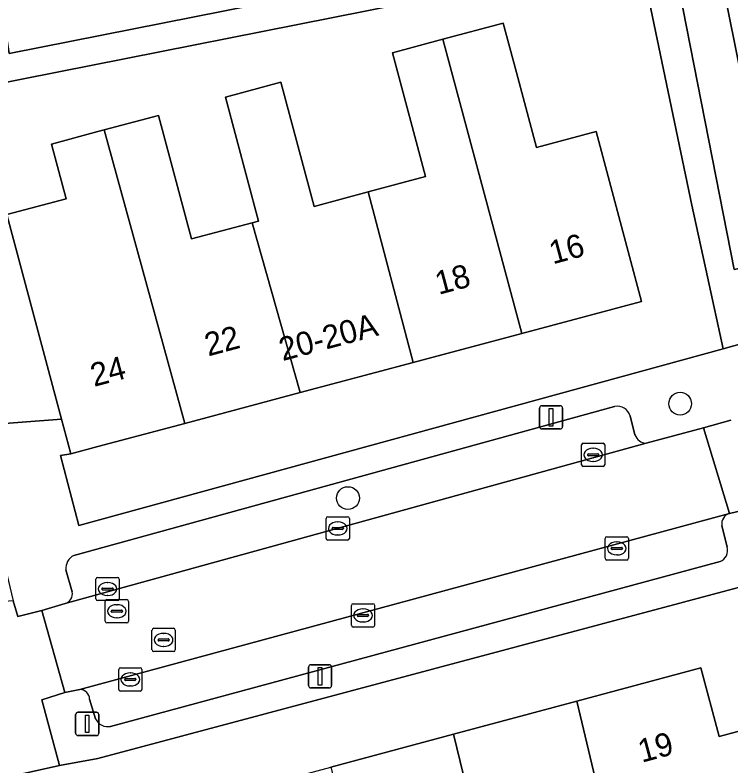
# Model space of a CAD drawing. Extents: x 162250 to 162661, y 380743 to 381606.
# Drawn here: x 162496.44 to 162527.18, y 380950.97 to 380983.23 of the extents above; entities that cross this region are included whole.
import ezdxf

# ---------------------------------------------------------------- set-up
doc = ezdxf.new("R2010")
doc.units = 0
for name, color, linetype in [('IMGEO_Boom', 7, 'Continuous'), ('IMGEO_Erf', 7, 'Continuous'), ('IMGEO_Kolk', 7, 'Continuous'), ('IMGEO_Lichtmast', 7, 'Continuous'), ('IMGEO_Pand', 7, 'Continuous'), ('IMGEO_Pand_nummerreeks', 7, 'Continuous'), ('IMGEO_Parkeervlak_open', 7, 'Continuous'), ('IMGEO_Rijbaan_lokaal_open', 7, 'Continuous'), ('IMGEO_Rioolput', 7, 'Continuous'), ('IMGEO_Voetpad_open', 7, 'Continuous'), ('IMGEO_Woonerf_open', 7, 'Continuous')]:
    doc.layers.add(name, color=color, linetype=linetype)

msp = doc.modelspace()

# ---------------------------------------------------------------- linework, layer by layer
at = {"layer": 'IMGEO_Boom'}
for centre in [(162525.003, 380966.531), (162510.736, 380962.476)]:
    msp.add_circle(centre, 0.489, dxfattribs=at)
at = {"layer": 'IMGEO_Erf'}
for points in [[(162496.082, 380974.653), (162498.633, 380975.335), (162498.004, 380977.689), (162500, 380978.222), (162500.261, 380978.292), (162502.6, 380978.917), (162504.019, 380973.608), (162506.629, 380974.306), (162506.895, 380974.377), (162505.472, 380979.701), (162507.858, 380980.339), (162509.282, 380975.009), (162511.604, 380975.63), (162514.072, 380976.29), (162512.649, 380981.613), (162514.809, 380982.19), (162517.404, 380982.883), (162517.971, 380980.762), (162518.833, 380977.539), (162521.395, 380978.223), (162523.345, 380970.926), (162518.207, 380969.553), (162513.53, 380968.303), (162508.678, 380967.006), (162503.731, 380965.684), (162500, 380964.687), (162498.83, 380964.374), (162498.385, 380964.311), (162499.174, 380961.297), (162526.854, 380968.89), (162526.18, 380971.982), (162525.511, 380975.056), (162523.272, 380985.775)], [(162495.915, 380983.354), (162496.184, 380981.582), (162509.432, 380984.21)], [(162514.514, 380984.008), (162495.265, 380980.189)], [(162528.738, 380958.965), (162500, 380951.285), (162498.35, 380950.984), (162494.027, 380950.024), (162442.323, 380945.804)], [(162495.389, 380946.986), (162499.152, 380947.998), (162500, 380948.226), (162504.51, 380949.437), (162510.003, 380950.912), (162515.265, 380952.326), (162520.561, 380953.748), (162525.886, 380955.178), (162526.677, 380952.231), (162529.874, 380953.09)]]:
    msp.add_lwpolyline(points, dxfattribs=at)
at = {"layer": 'IMGEO_Kolk'}
for p, q in [((162520.84, 380964.834), (162521.692, 380964.834)), ((162520.765, 380963.908), (162520.765, 380964.76)), ((162521.253, 380964.614), (162521.278, 380964.614)), ((162521.766, 380964.76), (162521.766, 380963.908)), ((162521.024, 380964.328), (162521.024, 380964.34)), ((162521.462, 380964.291), (162521.064, 380964.291)), ((162521.067, 380964.377), (162521.465, 380964.377)), ((162521.508, 380964.34), (162521.508, 380964.328)), ((162521.692, 380963.834), (162520.84, 380963.834)), ((162521.276, 380964.054), (162521.251, 380964.054)), ((162509.795, 380960.746), (162509.795, 380961.598)), ((162509.87, 380961.672), (162510.722, 380961.672)), ((162510.796, 380961.598), (162510.796, 380960.746)), ((162510.283, 380961.452), (162510.308, 380961.452)), ((162510.054, 380961.166), (162510.054, 380961.178)), ((162510.492, 380961.129), (162510.094, 380961.129)), ((162510.097, 380961.215), (162510.495, 380961.215)), ((162510.538, 380961.178), (162510.538, 380961.166)), ((162510.722, 380960.672), (162509.87, 380960.672)), ((162510.306, 380960.892), (162510.281, 380960.892)), ((162521.78, 380959.889), (162521.78, 380960.741)), ((162521.855, 380960.815), (162522.707, 380960.815)), ((162522.268, 380960.595), (162522.293, 380960.595)), ((162522.781, 380960.741), (162522.781, 380959.889)), ((162522.039, 380960.309), (162522.039, 380960.321)), ((162522.477, 380960.272), (162522.079, 380960.272)), ((162522.082, 380960.358), (162522.48, 380960.358)), ((162522.523, 380960.321), (162522.523, 380960.309)), ((162522.291, 380960.035), (162522.266, 380960.035)), ((162522.707, 380959.815), (162521.855, 380959.815)), ((162499.911, 380958.143), (162499.911, 380958.995)), ((162499.986, 380959.069), (162500.838, 380959.069)), ((162500.912, 380958.995), (162500.912, 380958.143)), ((162500.399, 380958.849), (162500.424, 380958.849)), ((162500.17, 380958.563), (162500.17, 380958.575)), ((162500.608, 380958.526), (162500.21, 380958.526)), ((162500.213, 380958.612), (162500.611, 380958.612)), ((162500.654, 380958.575), (162500.654, 380958.563)), ((162500.838, 380958.069), (162499.986, 380958.069)), ((162500.422, 380958.289), (162500.397, 380958.289)), ((162510.882, 380957.009), (162510.882, 380957.861)), ((162510.957, 380957.935), (162511.809, 380957.935)), ((162511.37, 380957.715), (162511.395, 380957.715)), ((162511.883, 380957.861), (162511.883, 380957.009)), ((162511.141, 380957.429), (162511.141, 380957.441)), ((162511.579, 380957.392), (162511.181, 380957.392)), ((162511.184, 380957.478), (162511.582, 380957.478)), ((162511.625, 380957.441), (162511.625, 380957.429)), ((162511.393, 380957.155), (162511.368, 380957.155)), ((162511.809, 380956.935), (162510.957, 380956.935)), ((162500.889, 380954.258), (162500.889, 380955.11)), ((162500.964, 380955.184), (162501.816, 380955.184)), ((162501.89, 380955.11), (162501.89, 380954.258)), ((162501.377, 380954.964), (162501.402, 380954.964)), ((162501.148, 380954.678), (162501.148, 380954.69)), ((162501.586, 380954.641), (162501.188, 380954.641)), ((162501.191, 380954.727), (162501.589, 380954.727)), ((162501.632, 380954.69), (162501.632, 380954.678)), ((162501.816, 380954.184), (162500.964, 380954.184)), ((162501.4, 380954.404), (162501.375, 380954.404))]:
    msp.add_line(p, q, dxfattribs=at)
for points in [[(162520.84, 380964.834), (162521.692, 380964.834)], [(162520.765, 380963.908), (162520.765, 380964.76)], [(162521.766, 380964.76), (162521.766, 380963.908)], [(162521.692, 380963.834), (162520.84, 380963.834)], [(162509.795, 380960.746), (162509.795, 380961.598)], [(162509.87, 380961.672), (162510.722, 380961.672)], [(162510.796, 380961.598), (162510.796, 380960.746)], [(162510.722, 380960.672), (162509.87, 380960.672)], [(162521.78, 380959.889), (162521.78, 380960.741)], [(162521.855, 380960.815), (162522.707, 380960.815)], [(162522.781, 380960.741), (162522.781, 380959.889)], [(162522.707, 380959.815), (162521.855, 380959.815)], [(162499.911, 380958.143), (162499.911, 380958.995)], [(162499.986, 380959.069), (162500.838, 380959.069)], [(162500.912, 380958.995), (162500.912, 380958.143)], [(162500.838, 380958.069), (162499.986, 380958.069)], [(162510.882, 380957.009), (162510.882, 380957.861)], [(162510.957, 380957.935), (162511.809, 380957.935)], [(162511.883, 380957.861), (162511.883, 380957.009)], [(162511.809, 380956.935), (162510.957, 380956.935)], [(162500.889, 380954.258), (162500.889, 380955.11)], [(162500.964, 380955.184), (162501.816, 380955.184)], [(162501.89, 380955.11), (162501.89, 380954.258)], [(162501.816, 380954.184), (162500.964, 380954.184)]]:
    msp.add_lwpolyline(points, dxfattribs=at)
for centre, radius, start, end in [((162520.842, 380964.758), 0.0765, 91.552, 178.448), ((162520.842, 380964.758), 0.0765, 91.552, 178.448), ((162521.69, 380964.758), 0.0765, 1.552, 88.448), ((162521.69, 380964.758), 0.0765, 1.552, 88.448), ((162521.064, 380964.337), 0.0403, 85.8775, 175.7526), ((162521.061, 380964.327), 0.0366, 178.938, 274.7102), ((162521.465, 380964.334), 0.043, 264.8664, 352.4533), ((162521.469, 380964.339), 0.0386, 1.7309, 96.639), ((162520.842, 380963.91), 0.0765, 181.552, 268.448), ((162520.842, 380963.91), 0.0765, 181.552, 268.448), ((162521.69, 380963.91), 0.0765, 271.552, 358.448), ((162521.69, 380963.91), 0.0765, 271.552, 358.448), ((162509.872, 380961.596), 0.0765, 91.552, 178.448), ((162509.872, 380961.596), 0.0765, 91.552, 178.448), ((162510.72, 380961.596), 0.0765, 1.552, 88.448), ((162510.72, 380961.596), 0.0765, 1.552, 88.448), ((162510.094, 380961.175), 0.0403, 85.8775, 175.7526), ((162510.091, 380961.165), 0.0366, 178.938, 274.7102), ((162510.495, 380961.172), 0.043, 264.8664, 352.4533), ((162510.499, 380961.177), 0.0386, 1.7309, 96.639), ((162509.872, 380960.748), 0.0765, 181.552, 268.448), ((162509.872, 380960.748), 0.0765, 181.552, 268.448), ((162510.72, 380960.748), 0.0765, 271.552, 358.448), ((162510.72, 380960.748), 0.0765, 271.552, 358.448), ((162521.857, 380960.739), 0.0765, 91.552, 178.448), ((162521.857, 380960.739), 0.0765, 91.552, 178.448), ((162522.705, 380960.739), 0.0765, 1.552, 88.448), ((162522.705, 380960.739), 0.0765, 1.552, 88.448), ((162522.079, 380960.318), 0.0403, 85.8775, 175.7526), ((162522.076, 380960.308), 0.0366, 178.938, 274.7102), ((162522.48, 380960.315), 0.043, 264.8664, 352.4533), ((162522.484, 380960.32), 0.0386, 1.7309, 96.639), ((162521.857, 380959.891), 0.0765, 181.552, 268.448), ((162521.857, 380959.891), 0.0765, 181.552, 268.448), ((162522.705, 380959.891), 0.0765, 271.552, 358.448), ((162522.705, 380959.891), 0.0765, 271.552, 358.448), ((162499.988, 380958.993), 0.0765, 91.552, 178.448), ((162499.988, 380958.993), 0.0765, 91.552, 178.448), ((162500.836, 380958.993), 0.0765, 1.552, 88.448), ((162500.836, 380958.993), 0.0765, 1.552, 88.448), ((162500.21, 380958.572), 0.0403, 85.8775, 175.7526), ((162500.207, 380958.562), 0.0366, 178.938, 274.7102), ((162500.611, 380958.569), 0.043, 264.8664, 352.4533), ((162500.615, 380958.574), 0.0386, 1.7309, 96.639), ((162499.988, 380958.145), 0.0765, 181.552, 268.448), ((162499.988, 380958.145), 0.0765, 181.552, 268.448), ((162500.836, 380958.145), 0.0765, 271.552, 358.448), ((162500.836, 380958.145), 0.0765, 271.552, 358.448), ((162510.959, 380957.859), 0.0765, 91.552, 178.448), ((162510.959, 380957.859), 0.0765, 91.552, 178.448), ((162511.807, 380957.859), 0.0765, 1.552, 88.448), ((162511.807, 380957.859), 0.0765, 1.552, 88.448), ((162511.181, 380957.438), 0.0403, 85.8775, 175.7526), ((162511.178, 380957.428), 0.0366, 178.938, 274.7102), ((162511.582, 380957.435), 0.043, 264.8664, 352.4533), ((162511.586, 380957.44), 0.0386, 1.7309, 96.639), ((162510.959, 380957.011), 0.0765, 181.552, 268.448), ((162510.959, 380957.011), 0.0765, 181.552, 268.448), ((162511.807, 380957.011), 0.0765, 271.552, 358.448), ((162511.807, 380957.011), 0.0765, 271.552, 358.448), ((162500.966, 380955.108), 0.0765, 91.552, 178.448), ((162500.966, 380955.108), 0.0765, 91.552, 178.448), ((162501.814, 380955.108), 0.0765, 1.552, 88.448), ((162501.814, 380955.108), 0.0765, 1.552, 88.448), ((162501.188, 380954.687), 0.0403, 85.8775, 175.7526), ((162501.185, 380954.677), 0.0366, 178.938, 274.7102), ((162501.589, 380954.684), 0.043, 264.8664, 352.4533), ((162501.593, 380954.689), 0.0386, 1.7309, 96.639), ((162500.966, 380954.26), 0.0765, 181.552, 268.448), ((162500.966, 380954.26), 0.0765, 181.552, 268.448), ((162501.814, 380954.26), 0.0765, 271.552, 358.448), ((162501.814, 380954.26), 0.0765, 271.552, 358.448)]:
    msp.add_arc(centre, radius, start, end, dxfattribs=at)
for centre, major_axis, ratio, start_param, end_param in [((162521.252, 380964.334), (-0.387, 0.002), 0.722429, 4.712389, 7.853982), ((162521.277, 380964.334), (-0.39, 0.002), 0.717154, 1.570796, 4.712389), ((162510.282, 380961.172), (-0.387, 0.002), 0.722429, 4.712389, 7.853982), ((162510.307, 380961.172), (-0.39, 0.002), 0.717154, 1.570796, 4.712389), ((162522.267, 380960.315), (-0.387, 0.002), 0.722429, 4.712389, 7.853982), ((162522.292, 380960.315), (-0.39, 0.002), 0.717154, 1.570796, 4.712389), ((162500.398, 380958.569), (-0.387, 0.002), 0.722429, 4.712389, 7.853982), ((162500.423, 380958.569), (-0.39, 0.002), 0.717154, 1.570796, 4.712389), ((162511.369, 380957.435), (-0.387, 0.002), 0.722429, 4.712389, 7.853982), ((162511.394, 380957.435), (-0.39, 0.002), 0.717154, 1.570796, 4.712389), ((162501.376, 380954.684), (-0.387, 0.002), 0.722429, 4.712389, 7.853982), ((162501.401, 380954.684), (-0.39, 0.002), 0.717154, 1.570796, 4.712389)]:
    msp.add_ellipse(centre, major_axis=major_axis, ratio=ratio, start_param=start_param, end_param=end_param, dxfattribs=at)
at = {"layer": 'IMGEO_Lichtmast'}
for p, q in [((162519.064, 380966.446), (162519.854, 380966.446)), ((162519.854, 380966.446), (162519.064, 380966.446)), ((162518.964, 380965.546), (162518.964, 380966.346)), ((162518.964, 380966.346), (162518.964, 380965.546)), ((162519.954, 380966.346), (162519.954, 380965.546)), ((162519.954, 380965.546), (162519.954, 380966.346)), ((162519.854, 380965.446), (162519.064, 380965.446)), ((162519.064, 380965.446), (162519.854, 380965.446)), ((162509.043, 380954.417), (162509.043, 380955.217)), ((162509.043, 380955.217), (162509.043, 380954.417)), ((162509.143, 380955.317), (162509.933, 380955.317)), ((162509.933, 380955.317), (162509.143, 380955.317)), ((162510.033, 380955.217), (162510.033, 380954.417)), ((162510.033, 380954.417), (162510.033, 380955.217)), ((162509.933, 380954.317), (162509.143, 380954.317)), ((162509.143, 380954.317), (162509.933, 380954.317)), ((162499.042, 380952.373), (162499.042, 380953.173)), ((162499.042, 380953.173), (162499.042, 380952.373)), ((162499.142, 380953.273), (162499.932, 380953.273)), ((162499.932, 380953.273), (162499.142, 380953.273)), ((162500.032, 380953.173), (162500.032, 380952.373)), ((162500.032, 380952.373), (162500.032, 380953.173)), ((162499.932, 380952.273), (162499.142, 380952.273)), ((162499.142, 380952.273), (162499.932, 380952.273))]:
    msp.add_line(p, q, dxfattribs=at)
for points in [[(162519.384, 380966.321), (162519.534, 380966.321), (162519.534, 380965.571), (162519.384, 380965.571), (162519.384, 380966.321)], [(162509.463, 380955.192), (162509.613, 380955.192), (162509.613, 380954.442), (162509.463, 380954.442), (162509.463, 380955.192)], [(162499.462, 380953.148), (162499.612, 380953.148), (162499.612, 380952.398), (162499.462, 380952.398), (162499.462, 380953.148)]]:
    msp.add_lwpolyline(points, dxfattribs=at)
for centre, start, end in [((162519.064, 380966.346), 90, 180), ((162519.064, 380966.346), 90, 180), ((162519.854, 380966.346), 0, 90), ((162519.854, 380966.346), 360, 90), ((162519.064, 380965.546), 180, 270), ((162519.064, 380965.546), 180, 270), ((162519.854, 380965.546), 270, 0), ((162519.854, 380965.546), 270, 0), ((162509.143, 380955.217), 90, 180), ((162509.143, 380955.217), 90, 180), ((162509.933, 380955.217), 0, 90), ((162509.933, 380955.217), 360, 90), ((162509.143, 380954.417), 180, 270), ((162509.143, 380954.417), 180, 270), ((162509.933, 380954.417), 270, 0), ((162509.933, 380954.417), 270, 0), ((162499.142, 380953.173), 90, 180), ((162499.142, 380953.173), 90, 180), ((162499.932, 380953.173), 0, 90), ((162499.932, 380953.173), 360, 90), ((162499.142, 380952.373), 180, 270), ((162499.142, 380952.373), 180, 270), ((162499.932, 380952.373), 270, 0), ((162499.932, 380952.373), 270, 0)]:
    msp.add_arc(centre, 0.1, start, end, dxfattribs=at)
at = {"layer": 'IMGEO_Pand'}
for points in [[(162521.395, 380978.223), (162518.833, 380977.539), (162517.971, 380980.762), (162517.404, 380982.883), (162514.809, 380982.19), (162518.207, 380969.553), (162523.345, 380970.926)], [(162513.53, 380968.303), (162518.207, 380969.553), (162514.809, 380982.19), (162512.649, 380981.613), (162514.072, 380976.29), (162511.604, 380975.63)], [(162511.604, 380975.63), (162509.282, 380975.009), (162507.858, 380980.339), (162505.472, 380979.701), (162506.895, 380974.377), (162506.629, 380974.306), (162508.678, 380967.006), (162513.53, 380968.303)], [(162500.261, 380978.292), (162503.731, 380965.684), (162508.678, 380967.006), (162506.629, 380974.306), (162504.019, 380973.608), (162502.6, 380978.917)], [(162500.261, 380978.292), (162500, 380978.222), (162498.004, 380977.689), (162498.633, 380975.335), (162496.082, 380974.653), (162498.432, 380965.863), (162498.83, 380964.374), (162500, 380964.687), (162503.731, 380965.684)], [(162520.561, 380953.748), (162522.426, 380945.934), (162523.141, 380946.126), (162527.397, 380947.269), (162527.733, 380946.022), (162531.067, 380946.918), (162530.28, 380950.99), (162529.874, 380953.09), (162526.677, 380952.231), (162525.886, 380955.178)], [(162520.561, 380953.748), (162515.265, 380952.326), (162517.177, 380944.524), (162520.411, 380945.393), (162521.219, 380942.384), (162523.234, 380942.925), (162522.426, 380945.934)], [(162515.265, 380952.326), (162510.003, 380950.912), (162512.001, 380943.135), (162512.845, 380939.991), (162515.878, 380940.806), (162515.034, 380943.949), (162517.177, 380944.524)]]:
    msp.add_lwpolyline(points, close=True, dxfattribs=at)
at = {"layer": 'IMGEO_Parkeervlak_open'}
msp.add_lwpolyline([(162529.238, 380972.673), (162529.173, 380972.977), (162526.498, 380986.245), (162524.664, 380985.878), (162527.328, 380972.293)], close=True, dxfattribs=at)
for points in [[(162522.19, 380966.408), (162498.968, 380960.008)], [(162523.061, 380965.191), (162522.854, 380966.006)], [(162498.589, 380957.94), (162523.548, 380964.83)], [(162527.124, 380961.813), (162499.225, 380954.254)], [(162527.018, 380960.373), (162526.793, 380961.294)], [(162500.545, 380952.667), (162526.717, 380959.747)], [(162498.623, 380959.391), (162498.897, 380958.452)], [(162499.64, 380953.834), (162499.894, 380952.989)]]:
    msp.add_lwpolyline(points, dxfattribs=at)
for centre, radius, start, end in [((162522.309, 380965.856), 0.565, 15.4327, 102.1841), ((162523.576, 380965.377), 0.548, 199.8554, 267.0475), ((162527.247, 380961.369), 0.46, 105.5077, 189.4357), ((162526.521, 380960.226), 0.518, 292.201, 16.4396), ((162499.224, 380959.46), 0.605, 115.0555, 186.5204), ((162498.45, 380958.372), 0.454, 287.815, 10.1259), ((162499.207, 380953.822), 0.433, 1.6475, 87.6663), ((162500.433, 380953.26), 0.604, 206.7057, 280.6581)]:
    msp.add_arc(centre, radius, start, end, dxfattribs=at)
at = {"layer": 'IMGEO_Rijbaan_lokaal_open'}
msp.add_lwpolyline([(162527.185, 380965.829), (162526.007, 380965.497), (162527.124, 380961.813), (162528.084, 380962.039)], dxfattribs=at)
for points in [[(162527.124, 380961.813), (162526.007, 380965.497), (162523.548, 380964.83), (162498.589, 380957.94), (162497.59, 380957.646), (162498.576, 380954.116), (162499.225, 380954.254)], [(162438.734, 380949.347), (162439.723, 380949.226), (162439.832, 380947.218), (162439.893, 380946.084), (162442.323, 380945.804), (162494.027, 380950.024), (162498.35, 380950.984), (162497.589, 380953.806), (162498.576, 380954.116), (162497.59, 380957.646), (162496.558, 380957.39), (162496.357, 380958.063), (162439.259, 380953.604), (162439.321, 380953.087), (162438.396, 380953.171), (162438.711, 380949.35)]]:
    msp.add_lwpolyline(points, close=True, dxfattribs=at)
at = {"layer": 'IMGEO_Rioolput'}
for p, q in [((162500.313, 380957.187), (162500.313, 380958.039)), ((162500.388, 380958.113), (162501.24, 380958.113)), ((162501.314, 380958.039), (162501.314, 380957.187)), ((162500.801, 380957.893), (162500.826, 380957.893)), ((162500.572, 380957.607), (162500.572, 380957.619)), ((162501.01, 380957.57), (162500.612, 380957.57)), ((162500.615, 380957.656), (162501.013, 380957.656)), ((162501.056, 380957.619), (162501.056, 380957.607)), ((162501.24, 380957.113), (162500.388, 380957.113)), ((162500.824, 380957.333), (162500.799, 380957.333)), ((162502.32, 380955.956), (162502.32, 380956.808)), ((162502.395, 380956.882), (162503.247, 380956.882)), ((162503.321, 380956.808), (162503.321, 380955.956)), ((162502.622, 380956.425), (162503.02, 380956.425)), ((162502.808, 380956.662), (162502.833, 380956.662)), ((162502.579, 380956.376), (162502.579, 380956.388)), ((162503.017, 380956.339), (162502.619, 380956.339)), ((162502.831, 380956.102), (162502.806, 380956.102)), ((162503.063, 380956.388), (162503.063, 380956.376)), ((162503.247, 380955.882), (162502.395, 380955.882))]:
    msp.add_line(p, q, dxfattribs=at)
for points in [[(162500.313, 380957.187), (162500.313, 380958.039)], [(162500.388, 380958.113), (162501.24, 380958.113)], [(162501.314, 380958.039), (162501.314, 380957.187)], [(162501.24, 380957.113), (162500.388, 380957.113)], [(162502.32, 380955.956), (162502.32, 380956.808)], [(162502.395, 380956.882), (162503.247, 380956.882)], [(162503.321, 380956.808), (162503.321, 380955.956)], [(162503.247, 380955.882), (162502.395, 380955.882)]]:
    msp.add_lwpolyline(points, dxfattribs=at)
for centre, radius, start, end in [((162500.39, 380958.037), 0.0765, 91.552, 178.448), ((162500.39, 380958.037), 0.0765, 91.552, 178.448), ((162501.238, 380958.037), 0.0765, 1.552, 88.448), ((162501.238, 380958.037), 0.0765, 1.552, 88.448), ((162500.612, 380957.616), 0.0403, 85.8775, 175.7526), ((162500.609, 380957.606), 0.0366, 178.938, 274.7102), ((162501.013, 380957.613), 0.043, 264.8664, 352.4533), ((162501.017, 380957.618), 0.0386, 1.7309, 96.639), ((162500.39, 380957.189), 0.0765, 181.552, 268.448), ((162500.39, 380957.189), 0.0765, 181.552, 268.448), ((162501.238, 380957.189), 0.0765, 271.552, 358.448), ((162501.238, 380957.189), 0.0765, 271.552, 358.448), ((162502.397, 380956.806), 0.0765, 91.552, 178.448), ((162502.397, 380956.806), 0.0765, 91.552, 178.448), ((162503.245, 380956.806), 0.0765, 1.552, 88.448), ((162503.245, 380956.806), 0.0765, 1.552, 88.448), ((162502.619, 380956.385), 0.0403, 85.8775, 175.7526), ((162503.024, 380956.387), 0.0386, 1.7309, 96.639), ((162502.616, 380956.375), 0.0366, 178.938, 274.7102), ((162503.02, 380956.382), 0.043, 264.8664, 352.4533), ((162502.397, 380955.958), 0.0765, 181.552, 268.448), ((162502.397, 380955.958), 0.0765, 181.552, 268.448), ((162503.245, 380955.958), 0.0765, 271.552, 358.448), ((162503.245, 380955.958), 0.0765, 271.552, 358.448)]:
    msp.add_arc(centre, radius, start, end, dxfattribs=at)
for centre, major_axis, ratio, start_param, end_param in [((162500.8, 380957.613), (-0.387, 0.002), 0.722429, 4.712389, 7.853982), ((162500.825, 380957.613), (-0.39, 0.002), 0.717154, 1.570796, 4.712389), ((162502.807, 380956.382), (-0.387, 0.002), 0.722429, 4.712389, 7.853982), ((162502.832, 380956.382), (-0.39, 0.002), 0.717154, 1.570796, 4.712389)]:
    msp.add_ellipse(centre, major_axis=major_axis, ratio=ratio, start_param=start_param, end_param=end_param, dxfattribs=at)
at = {"layer": 'IMGEO_Voetpad_open'}
for points in [[(162514.276, 381037.726), (162513.922, 381039.54), (162512.477, 381039.235), (162520.3, 381000), (162523.029, 380986.937), (162523.272, 380985.775), (162525.511, 380975.056), (162526.18, 380971.982), (162526.854, 380968.89), (162529.804, 380969.718)], [(162529.652, 380970.821), (162529.238, 380972.673), (162527.328, 380972.293), (162524.664, 380985.878), (162526.498, 380986.245), (162526.262, 380987.458), (162524.476, 380987.064), (162514.276, 381037.726)], [(162493.737, 380985.206), (162494.009, 380981.627), (162494.429, 380976.113), (162494.62, 380973.605), (162494.999, 380968.619), (162495.227, 380965.622), (162498.432, 380965.863), (162496.082, 380974.653), (162495.468, 380976.95), (162495.265, 380980.189), (162514.514, 380984.008)], [(162509.432, 380984.21), (162496.184, 380981.582), (162495.915, 380983.354)], [(162529.804, 380969.718), (162526.854, 380968.89), (162499.174, 380961.297), (162498.385, 380964.311)], [(162498.968, 380960.008), (162522.19, 380966.408)], [(162498.385, 380964.311), (162498.83, 380964.374), (162498.432, 380965.863), (162495.227, 380965.622), (162471.572, 380963.846), (162470.699, 380963.849), (162470.212, 380963.82), (162470.338, 380962.659), (162483.148, 380963.671), (162483.168, 380963.025), (162485.706, 380963.237), (162485.657, 380963.842), (162495.7, 380964.636), (162496.019, 380959.507), (162496.357, 380958.063), (162496.558, 380957.39), (162497.59, 380957.646), (162498.589, 380957.94)], [(162522.854, 380966.006), (162523.061, 380965.191)], [(162523.548, 380964.83), (162526.007, 380965.497), (162527.185, 380965.829)], [(162528.084, 380962.039), (162527.124, 380961.813)], [(162526.793, 380961.294), (162527.018, 380960.373)], [(162499.225, 380954.254), (162498.576, 380954.116), (162497.589, 380953.806), (162498.35, 380950.984), (162500, 380951.285), (162528.738, 380958.965), (162532.735, 380959.888)], [(162526.717, 380959.747), (162500.545, 380952.667)], [(162498.897, 380958.452), (162498.623, 380959.391)], [(162499.894, 380952.989), (162499.64, 380953.834)]]:
    msp.add_lwpolyline(points, dxfattribs=at)
for centre, radius, start, end in [((162522.309, 380965.856), 0.565, 15.4327, 102.1841), ((162523.576, 380965.377), 0.548, 199.8554, 267.0475), ((162527.247, 380961.369), 0.46, 105.5077, 189.4357), ((162526.521, 380960.226), 0.518, 292.201, 16.4396), ((162499.224, 380959.46), 0.605, 115.0555, 186.5204), ((162498.45, 380958.372), 0.454, 287.815, 10.1259), ((162499.207, 380953.822), 0.433, 1.6475, 87.6663), ((162500.433, 380953.26), 0.604, 206.7057, 280.6581)]:
    msp.add_arc(centre, radius, start, end, dxfattribs=at)
at = {"layer": 'IMGEO_Woonerf_open'}
msp.add_lwpolyline([(162530.338, 380986.31), (162527.982, 380998.093), (162524.286, 380997.353), (162526.262, 380987.458), (162526.498, 380986.245), (162529.173, 380972.977), (162532.879, 380973.707), (162532.831, 380973.854), (162530.682, 380984.53)], close=True, dxfattribs=at)

# ---------------------------------------------------------------- texts
at = {"layer": 'IMGEO_Pand_nummerreeks'}
for s, rotation, p in [('16', 14.9657, (162519.533, 380972.516)), ('18', 14.9634, (162514.632, 380971.205)), ('20-20A', 14.9657, (162507.929, 380968.358)), ('22', 14.9634, (162504.733, 380968.559)), ('24', 14.9649, (162499.833, 380967.251)), ('19', 15.0334, (162523.353, 380951.101))]:
    msp.add_text(s, height=1, rotation=rotation, dxfattribs=at).set_placement(p)

doc.saveas('drawing.dxf')
